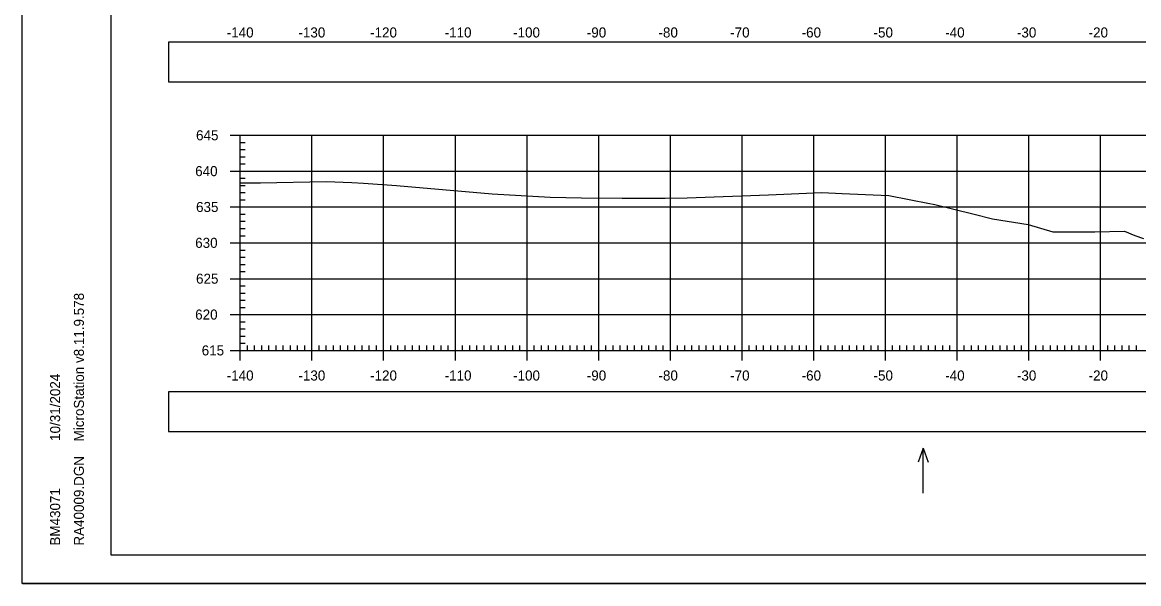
# Model space of a CAD drawing. Extents: x 1381471 to 1382703, y 370300 to 371487.
# Drawn here: x 1381834.4 to 1381990.1, y 370334.3 to 370412.6 of the extents above; entities that cross this region are included whole.
import ezdxf

# ---------------------------------------------------------------- set-up
doc = ezdxf.new("R2010")
doc.units = 0
for name, color, linetype in [('Level 18', 7, 'Continuous'), ('Level 22', 7, 'Continuous'), ('Level 26', 7, 'Continuous'), ('Level 4', 7, 'Continuous'), ('Level 40', 7, 'Continuous'), ('Level 5', 7, 'Continuous'), ('Level 6', 7, 'Continuous')]:
    doc.layers.add(name, color=color, linetype=linetype)

msp = doc.modelspace()

# ---------------------------------------------------------------- linework, layer by layer
at = {"layer": 'Level 18'}
msp.add_lwpolyline([(1381864.77, 370390.21), (1381865.08, 370390.21), (1381867.59, 370390.19), (1381876.76, 370390.38), (1381880.34, 370390.24), (1381881.94, 370390.12), (1381886.55, 370389.8), (1381899.9, 370388.65), (1381907.99, 370388.19), (1381912.37, 370388.12), (1381918.05, 370388.03), (1381924.05, 370388.04), (1381927.12, 370388.11), (1381938.45, 370388.51), (1381945.9, 370388.84), (1381948.73, 370388.71), (1381955.26, 370388.41), (1381960.92, 370387.32), (1381961.42, 370387.23), (1381961.66, 370387.18), (1381967.16, 370385.84), (1381969.71, 370385.19), (1381974.66, 370384.36), (1381978.13, 370383.36), (1381984, 370383.35), (1381988.11, 370383.47), (1381989.55, 370382.84), (1381990.78, 370382.43)], dxfattribs=at)
at = {"layer": 'Level 22'}
for p, q in [((1381864.77, 370396.82), (1382144.77, 370396.82)), ((1381864.77, 370366.82), (1381864.77, 370396.82)), ((1381874.77, 370366.82), (1381874.77, 370396.82)), ((1381884.77, 370366.82), (1381884.77, 370396.82)), ((1381894.77, 370366.82), (1381894.77, 370396.82)), ((1381904.77, 370366.82), (1381904.77, 370396.82)), ((1381914.77, 370366.82), (1381914.77, 370396.82)), ((1381924.77, 370366.82), (1381924.77, 370396.82)), ((1381934.77, 370366.82), (1381934.77, 370396.82)), ((1381944.77, 370366.82), (1381944.77, 370396.82)), ((1381954.77, 370366.82), (1381954.77, 370396.82)), ((1381964.77, 370366.82), (1381964.77, 370396.82)), ((1381974.77, 370366.82), (1381974.77, 370396.82)), ((1381984.77, 370366.82), (1381984.77, 370396.82)), ((1381864.77, 370391.82), (1382144.77, 370391.82)), ((1381864.77, 370386.82), (1382144.77, 370386.82)), ((1381864.77, 370381.82), (1382144.77, 370381.82)), ((1381864.77, 370376.82), (1382144.77, 370376.82)), ((1381864.77, 370371.82), (1382144.77, 370371.82)), ((1381864.77, 370366.82), (1382144.77, 370366.82))]:
    msp.add_line(p, q, dxfattribs=at)
at = {"layer": 'Level 26'}
msp.add_line((1381834.37, 370334.29), (1382167.7, 370334.29), dxfattribs=at)
for points in [[(1381834.36, 370547.63), (1382167.7, 370547.63), (1382167.7, 370334.29), (1381834.36, 370334.29)], [(1382080.69, 370543.73), (1382100.31, 370543.73), (1382100.31, 370533.85), (1382116.42, 370533.85), (1382139.62, 370533.85), (1382139.62, 370501.18), (1382162.83, 370501.18), (1382162.95, 370338.27), (1381846.77, 370338.27), (1381846.77, 370543.73)]]:
    msp.add_lwpolyline(points, close=True, dxfattribs=at)
at = {"layer": 'Level 4'}
for p, q in [((1381863.37, 370396.82), (1381866.17, 370396.82)), ((1381864.77, 370366.82), (1381864.77, 370396.82)), ((1381864.77, 370395.82), (1381865.47, 370395.82)), ((1381864.77, 370394.82), (1381865.47, 370394.82)), ((1381864.77, 370393.82), (1381865.47, 370393.82)), ((1381864.77, 370392.82), (1381865.47, 370392.82)), ((1381863.37, 370391.82), (1381866.17, 370391.82)), ((1381864.77, 370390.82), (1381865.47, 370390.82)), ((1381864.77, 370389.82), (1381865.47, 370389.82)), ((1381864.77, 370388.82), (1381865.47, 370388.82)), ((1381864.77, 370387.82), (1381865.47, 370387.82)), ((1381863.37, 370386.82), (1381866.17, 370386.82)), ((1381864.77, 370385.82), (1381865.47, 370385.82)), ((1381864.77, 370384.82), (1381865.47, 370384.82)), ((1381864.77, 370383.82), (1381865.47, 370383.82)), ((1381863.37, 370381.82), (1381866.17, 370381.82)), ((1381864.77, 370382.82), (1381865.47, 370382.82)), ((1381864.77, 370380.82), (1381865.47, 370380.82)), ((1381864.77, 370379.82), (1381865.47, 370379.82)), ((1381864.77, 370378.82), (1381865.47, 370378.82)), ((1381863.37, 370376.82), (1381866.17, 370376.82)), ((1381864.77, 370377.82), (1381865.47, 370377.82)), ((1381864.77, 370375.82), (1381865.47, 370375.82)), ((1381864.77, 370374.82), (1381865.47, 370374.82)), ((1381864.77, 370373.82), (1381865.47, 370373.82)), ((1381864.77, 370372.82), (1381865.47, 370372.82)), ((1381863.37, 370371.82), (1381866.17, 370371.82)), ((1381864.77, 370370.82), (1381865.47, 370370.82)), ((1381864.77, 370369.82), (1381865.47, 370369.82)), ((1381864.77, 370368.82), (1381865.47, 370368.82)), ((1381864.77, 370365.42), (1381864.77, 370368.22)), ((1381864.77, 370367.82), (1381865.47, 370367.82)), ((1381865.77, 370366.82), (1381865.77, 370367.52)), ((1381866.77, 370366.82), (1381866.77, 370367.52)), ((1381867.77, 370366.82), (1381867.77, 370367.52)), ((1381868.77, 370366.82), (1381868.77, 370367.52)), ((1381869.77, 370366.82), (1381869.77, 370367.52)), ((1381870.77, 370366.82), (1381870.77, 370367.52)), ((1381871.77, 370366.82), (1381871.77, 370367.52)), ((1381872.77, 370366.82), (1381872.77, 370367.52)), ((1381873.77, 370366.82), (1381873.77, 370367.52)), ((1381874.77, 370365.42), (1381874.77, 370368.22)), ((1381875.77, 370366.82), (1381875.77, 370367.52)), ((1381876.77, 370366.82), (1381876.77, 370367.52)), ((1381877.77, 370366.82), (1381877.77, 370367.52)), ((1381878.77, 370366.82), (1381878.77, 370367.52)), ((1381879.77, 370366.82), (1381879.77, 370367.52)), ((1381880.77, 370366.82), (1381880.77, 370367.52)), ((1381881.77, 370366.82), (1381881.77, 370367.52)), ((1381882.77, 370366.82), (1381882.77, 370367.52)), ((1381883.77, 370366.82), (1381883.77, 370367.52)), ((1381884.77, 370365.42), (1381884.77, 370368.22)), ((1381885.77, 370366.82), (1381885.77, 370367.52)), ((1381886.77, 370366.82), (1381886.77, 370367.52)), ((1381887.77, 370366.82), (1381887.77, 370367.52)), ((1381888.77, 370366.82), (1381888.77, 370367.52)), ((1381889.77, 370366.82), (1381889.77, 370367.52)), ((1381890.77, 370366.82), (1381890.77, 370367.52)), ((1381891.77, 370366.82), (1381891.77, 370367.52)), ((1381892.77, 370366.82), (1381892.77, 370367.52)), ((1381893.77, 370366.82), (1381893.77, 370367.52)), ((1381894.77, 370365.42), (1381894.77, 370368.22)), ((1381895.77, 370366.82), (1381895.77, 370367.52)), ((1381896.77, 370366.82), (1381896.77, 370367.52)), ((1381897.77, 370366.82), (1381897.77, 370367.52)), ((1381898.77, 370366.82), (1381898.77, 370367.52)), ((1381899.77, 370366.82), (1381899.77, 370367.52)), ((1381900.77, 370366.82), (1381900.77, 370367.52)), ((1381901.77, 370366.82), (1381901.77, 370367.52)), ((1381902.77, 370366.82), (1381902.77, 370367.52)), ((1381903.77, 370366.82), (1381903.77, 370367.52)), ((1381904.77, 370365.42), (1381904.77, 370368.22)), ((1381905.77, 370366.82), (1381905.77, 370367.52)), ((1381906.77, 370366.82), (1381906.77, 370367.52)), ((1381907.77, 370366.82), (1381907.77, 370367.52)), ((1381908.77, 370366.82), (1381908.77, 370367.52)), ((1381909.77, 370366.82), (1381909.77, 370367.52)), ((1381910.77, 370366.82), (1381910.77, 370367.52)), ((1381911.77, 370366.82), (1381911.77, 370367.52)), ((1381912.77, 370366.82), (1381912.77, 370367.52)), ((1381913.77, 370366.82), (1381913.77, 370367.52)), ((1381914.77, 370365.42), (1381914.77, 370368.22)), ((1381915.77, 370366.82), (1381915.77, 370367.52)), ((1381916.77, 370366.82), (1381916.77, 370367.52)), ((1381917.77, 370366.82), (1381917.77, 370367.52)), ((1381918.77, 370366.82), (1381918.77, 370367.52)), ((1381919.77, 370366.82), (1381919.77, 370367.52)), ((1381920.77, 370366.82), (1381920.77, 370367.52)), ((1381921.77, 370366.82), (1381921.77, 370367.52)), ((1381922.77, 370366.82), (1381922.77, 370367.52)), ((1381923.77, 370366.82), (1381923.77, 370367.52)), ((1381924.77, 370365.42), (1381924.77, 370368.22)), ((1381925.77, 370366.82), (1381925.77, 370367.52)), ((1381926.77, 370366.82), (1381926.77, 370367.52)), ((1381927.77, 370366.82), (1381927.77, 370367.52)), ((1381928.77, 370366.82), (1381928.77, 370367.52)), ((1381929.77, 370366.82), (1381929.77, 370367.52)), ((1381930.77, 370366.82), (1381930.77, 370367.52)), ((1381931.77, 370366.82), (1381931.77, 370367.52)), ((1381932.77, 370366.82), (1381932.77, 370367.52)), ((1381933.77, 370366.82), (1381933.77, 370367.52)), ((1381934.77, 370365.42), (1381934.77, 370368.22)), ((1381935.77, 370366.82), (1381935.77, 370367.52)), ((1381936.77, 370366.82), (1381936.77, 370367.52)), ((1381937.77, 370366.82), (1381937.77, 370367.52)), ((1381938.77, 370366.82), (1381938.77, 370367.52)), ((1381939.77, 370366.82), (1381939.77, 370367.52)), ((1381940.77, 370366.82), (1381940.77, 370367.52)), ((1381941.77, 370366.82), (1381941.77, 370367.52)), ((1381942.77, 370366.82), (1381942.77, 370367.52)), ((1381943.77, 370366.82), (1381943.77, 370367.52)), ((1381944.77, 370365.42), (1381944.77, 370368.22)), ((1381945.77, 370366.82), (1381945.77, 370367.52)), ((1381946.77, 370366.82), (1381946.77, 370367.52)), ((1381947.77, 370366.82), (1381947.77, 370367.52)), ((1381948.77, 370366.82), (1381948.77, 370367.52)), ((1381949.77, 370366.82), (1381949.77, 370367.52)), ((1381950.77, 370366.82), (1381950.77, 370367.52)), ((1381951.77, 370366.82), (1381951.77, 370367.52)), ((1381952.77, 370366.82), (1381952.77, 370367.52)), ((1381953.77, 370366.82), (1381953.77, 370367.52)), ((1381954.77, 370365.42), (1381954.77, 370368.22)), ((1381955.77, 370366.82), (1381955.77, 370367.52)), ((1381956.77, 370366.82), (1381956.77, 370367.52)), ((1381957.77, 370366.82), (1381957.77, 370367.52)), ((1381958.77, 370366.82), (1381958.77, 370367.52)), ((1381959.77, 370366.82), (1381959.77, 370367.52)), ((1381960.77, 370366.82), (1381960.77, 370367.52)), ((1381961.77, 370366.82), (1381961.77, 370367.52)), ((1381962.77, 370366.82), (1381962.77, 370367.52)), ((1381963.77, 370366.82), (1381963.77, 370367.52)), ((1381964.77, 370365.42), (1381964.77, 370368.22)), ((1381965.77, 370366.82), (1381965.77, 370367.52)), ((1381966.77, 370366.82), (1381966.77, 370367.52)), ((1381967.77, 370366.82), (1381967.77, 370367.52)), ((1381968.77, 370366.82), (1381968.77, 370367.52)), ((1381969.77, 370366.82), (1381969.77, 370367.52)), ((1381970.77, 370366.82), (1381970.77, 370367.52)), ((1381971.77, 370366.82), (1381971.77, 370367.52)), ((1381972.77, 370366.82), (1381972.77, 370367.52)), ((1381973.77, 370366.82), (1381973.77, 370367.52)), ((1381974.77, 370365.42), (1381974.77, 370368.22)), ((1381975.77, 370366.82), (1381975.77, 370367.52)), ((1381976.77, 370366.82), (1381976.77, 370367.52)), ((1381977.77, 370366.82), (1381977.77, 370367.52)), ((1381978.77, 370366.82), (1381978.77, 370367.52)), ((1381979.77, 370366.82), (1381979.77, 370367.52)), ((1381980.77, 370366.82), (1381980.77, 370367.52)), ((1381981.77, 370366.82), (1381981.77, 370367.52)), ((1381982.77, 370366.82), (1381982.77, 370367.52)), ((1381983.77, 370366.82), (1381983.77, 370367.52)), ((1381984.77, 370365.42), (1381984.77, 370368.22)), ((1381985.77, 370366.82), (1381985.77, 370367.52)), ((1381986.77, 370366.82), (1381986.77, 370367.52)), ((1381987.77, 370366.82), (1381987.77, 370367.52)), ((1381988.77, 370366.82), (1381988.77, 370367.52)), ((1381989.77, 370366.82), (1381989.77, 370367.52)), ((1381863.37, 370366.82), (1381866.17, 370366.82)), ((1381864.77, 370366.82), (1382144.77, 370366.82))]:
    msp.add_line(p, q, dxfattribs=at)
at = {"layer": 'Level 40'}
for p, q in [((1381960.05, 370353.17), (1381959.35, 370351.25)), ((1381960.05, 370346.89), (1381960.05, 370353.17)), ((1381960.05, 370353.17), (1381960.75, 370351.25))]:
    msp.add_line(p, q, dxfattribs=at)
at = {"layer": 'Level 6'}
for p, q in [((1381846.77, 370338.27), (1381846.77, 370543.73)), ((1381846.77, 370338.27), (1381846.77, 370338.27)), ((1382162.95, 370338.27), (1381846.77, 370338.27))]:
    msp.add_line(p, q, dxfattribs=at)
for points in [[(1381854.77, 370404.27), (1382154.77, 370404.27), (1382154.77, 370409.8), (1381854.77, 370409.8)], [(1381854.77, 370355.52), (1382154.77, 370355.52), (1382154.77, 370361.04), (1381854.77, 370361.04)]]:
    msp.add_lwpolyline(points, close=True, dxfattribs=at)

# ---------------------------------------------------------------- texts
at = {"layer": 'Level 5'}
for s, p in [('-140', (1381862.88, 370410.46)), ('-130', (1381872.88, 370410.46)), ('-120', (1381882.88, 370410.46)), ('-110', (1381893.28, 370410.46)), ('-100', (1381902.83, 370410.46)), ('-90', (1381913.11, 370410.46)), ('-80', (1381923.11, 370410.46)), ('-70', (1381933.11, 370410.46)), ('-60', (1381943.08, 370410.46)), ('-50', (1381953.11, 370410.46)), ('-40', (1381963.11, 370410.46)), ('-30', (1381973.11, 370410.46)), ('-20', (1381983.11, 370410.46)), ('645', (1381858.6, 370396.12)), ('640', (1381858.48, 370391.12)), ('635', (1381858.6, 370386.12)), ('630', (1381858.48, 370381.12)), ('625', (1381858.6, 370376.12)), ('620', (1381858.48, 370371.12)), ('615', (1381859.39, 370366.12)), ('-140', (1381862.88, 370362.62)), ('-130', (1381872.88, 370362.62)), ('-120', (1381882.88, 370362.62)), ('-110', (1381893.28, 370362.62)), ('-100', (1381902.83, 370362.62)), ('-90', (1381913.11, 370362.62)), ('-80', (1381923.11, 370362.62)), ('-70', (1381933.11, 370362.62)), ('-60', (1381943.08, 370362.62)), ('-50', (1381953.11, 370362.62)), ('-40', (1381963.11, 370362.62)), ('-30', (1381973.11, 370362.62)), ('-20', (1381983.11, 370362.62))]:
    msp.add_text(s, height=1.4, dxfattribs=at).set_placement(p)
at = {"layer": 'Level 6'}
for s, p in [('MicroStation v8.11.9.578', (1381842.96, 370354.13)), ('10/31/2024', (1381839.64, 370354.2)), ('RA40009.DGN', (1381842.96, 370339.6)), ('BM43071', (1381839.64, 370339.6))]:
    msp.add_text(s, height=1.4, rotation=90, dxfattribs=at).set_placement(p)

doc.saveas('drawing.dxf')
